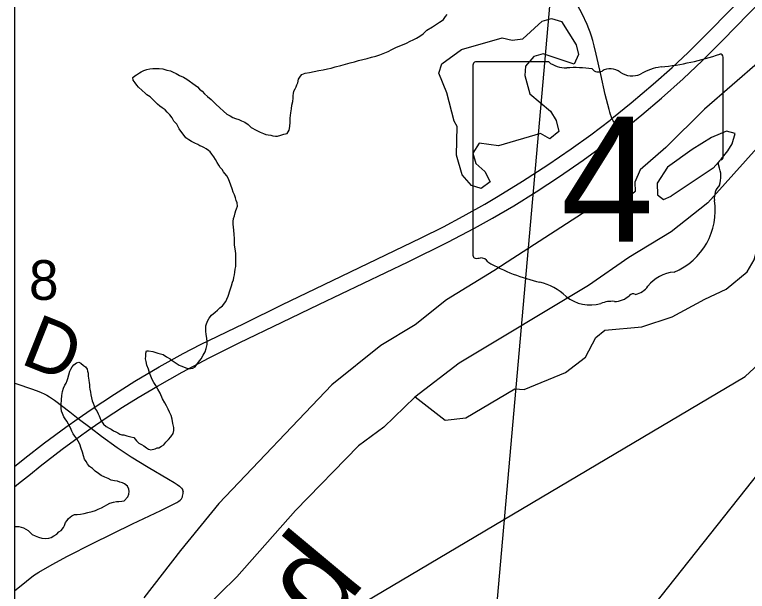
# Model space of a CAD drawing. Extents: x 0 to 34, y 0 to 22.
# Drawn here: x 22.516 to 23.289, y 17.166 to 17.774 of the extents above; entities that cross this region are included whole.
import ezdxf

# ---------------------------------------------------------------- set-up
doc = ezdxf.new("R2010")
doc.units = 0
for name, color, linetype in [('GM_X_County_Road', 7, 'Continuous'), ('GM_X_Major_River', 7, 'Continuous'), ('GM_X_Major_River_Text', 7, 'Continuous'), ('GM_X_Minor_Lake', 7, 'Continuous'), ('GM_X_Minor_River', 7, 'Continuous'), ('GM_X_Rail_Line', 7, 'Continuous'), ('GM_X_Section', 7, 'Continuous'), ('GM_X_Section_Text', 7, 'Continuous'), ('GM_X_State_Location', 7, 'Continuous'), ('GM_X_State_Route', 7, 'Continuous'), ('GM_X_State_Shield', 7, 'Continuous'), ('GM_X_Township_Road', 7, 'Continuous'), ('GM_X_Township_Road_Text', 7, 'Continuous'), ('SH_Border', 7, 'Continuous'), ('SH_Data', 7, 'Continuous')]:
    doc.layers.add(name, color=color, linetype=linetype)

msp = doc.modelspace()

# ---------------------------------------------------------------- linework, layer by layer
at = {"layer": 'GM_X_County_Road'}
msp.add_lwpolyline([(22.51637, 18.01675), (22.51637, 17.0024), (23.00697, 16.95129), (23.09601, 17.95858)], close=True, dxfattribs=at)
at = {"layer": 'GM_X_Major_River'}
for points in [[(23.30177, 17.72504), (23.24359, 17.67462), (23.20273, 17.63398), (23.17558, 17.61042), (23.16994, 17.59767), (23.17045, 17.58779), (23.15958, 17.57822), (23.13867, 17.57575), (23.11487, 17.56462), (23.03543, 17.51325), (23.02154, 17.50413), (22.97146, 17.4736), (22.93855, 17.44716), (22.90234, 17.42536), (22.85084, 17.38386), (22.73158, 17.25878), (22.69125, 17.20938), (22.65243, 17.15956)], [(23.31427, 17.65071), (23.24713, 17.57586), (23.20842, 17.5454), (23.16373, 17.51814), (23.12126, 17.48855), (22.98491, 17.40682), (22.9381, 17.37089), (22.90544, 17.3395), (22.87877, 17.31973), (22.81255, 17.25167), (22.75046, 17.1816), (22.71467, 17.1465), (22.65709, 17.07555), (22.63645, 17.05447), (22.62333, 17.04533), (22.57284, 17.02884), (22.56247, 17.01292)], [(23.25271, 17.61242), (23.26124, 17.62174), (23.26825, 17.63072), (23.27257, 17.63785), (23.27582, 17.6488), (23.26677, 17.65127), (23.25108, 17.64475), (23.23072, 17.63187), (23.20455, 17.61341), (23.19359, 17.59653), (23.1941, 17.58436), (23.20045, 17.57929), (23.20849, 17.58293)], [(23.25271, 17.61242), (23.20849, 17.58293)]]:
    msp.add_lwpolyline(points, dxfattribs=at)
at = {"layer": 'GM_X_Minor_Lake'}
for points in [[(22.97208, 17.6919), (22.96339, 17.71259), (22.96662, 17.72241), (22.98741, 17.73756), (23.03014, 17.7496), (23.04071, 17.7471), (23.05212, 17.74877), (23.0726, 17.76735), (23.08214, 17.77019), (23.0927, 17.76693), (23.10814, 17.7423), (23.11058, 17.73199), (23.10621, 17.72182), (23.07342, 17.73275), (23.0635, 17.72992), (23.05495, 17.71983), (23.054, 17.70997), (23.0593, 17.69087), (23.08132, 17.67255), (23.08718, 17.66256), (23.08999, 17.6511), (23.08035, 17.64332), (23.0706, 17.64883), (23.02633, 17.63606), (23.0059, 17.63876), (22.99925, 17.62826), (23.00244, 17.61717), (23.01213, 17.609), (23.0176, 17.59786), (23.00798, 17.59084), (22.9978, 17.59409), (22.98816, 17.60531), (22.98213, 17.62595), (22.98274, 17.65634), (22.97981, 17.66172)], [(22.97981, 17.66172), (22.97208, 17.6919)]]:
    msp.add_lwpolyline(points, dxfattribs=at)
at = {"layer": 'GM_X_Minor_River'}
for points in [[(22.91822, 17.73947), (22.9293, 17.74423), (22.93313, 17.74607), (22.93657, 17.74753), (22.94001, 17.74938), (22.94347, 17.7516), (22.94692, 17.75382), (22.95078, 17.75794), (22.95691, 17.76126), (22.96113, 17.76424), (22.9642, 17.76608), (22.96611, 17.76719), (22.96842, 17.76906), (22.97037, 17.77207), (22.9723, 17.77432)], [(22.66486, 17.68205), (22.66186, 17.68476), (22.65925, 17.68747), (22.65587, 17.6898), (22.65399, 17.69135), (22.65062, 17.69407), (22.64688, 17.69756), (22.64502, 17.69987), (22.64354, 17.70217), (22.64131, 17.70525), (22.64097, 17.70792), (22.6429, 17.70979), (22.64482, 17.7109), (22.64788, 17.71275), (22.6498, 17.71386), (22.65248, 17.71533), (22.65554, 17.71642), (22.65896, 17.71713), (22.66201, 17.71746), (22.66542, 17.7174), (22.66883, 17.71735), (22.67262, 17.7169), (22.67678, 17.71569), (22.68056, 17.71487), (22.68358, 17.71368), (22.68659, 17.71211), (22.68998, 17.71015), (22.6945, 17.70818), (22.69789, 17.70622), (22.70652, 17.7), (22.70915, 17.69805), (22.71139, 17.69573), (22.71401, 17.69341), (22.71662, 17.6907), (22.71962, 17.688), (22.72336, 17.68489), (22.7286, 17.67986), (22.73271, 17.67599), (22.73645, 17.67251), (22.7402, 17.66941), (22.74358, 17.66745), (22.74622, 17.66589), (22.74923, 17.66469), (22.75263, 17.6635), (22.75565, 17.66231), (22.75904, 17.66073), (22.76242, 17.65839), (22.76579, 17.6553), (22.77106, 17.65255), (22.7752, 17.6502), (22.77859, 17.649), (22.78123, 17.64782), (22.78351, 17.6474), (22.78653, 17.64697), (22.78842, 17.64656), (22.79145, 17.64613), (22.79335, 17.6461), (22.79679, 17.64718), (22.80022, 17.64827), (22.80365, 17.64897), (22.8056, 17.65236), (22.80642, 17.65615), (22.80687, 17.6607), (22.80694, 17.66489), (22.80741, 17.67058), (22.80823, 17.67475), (22.80868, 17.67892), (22.8095, 17.68271), (22.80993, 17.68613), (22.80998, 17.68879), (22.81039, 17.69106), (22.81081, 17.69334), (22.81199, 17.69598), (22.81317, 17.69824), (22.81396, 17.70013), (22.81475, 17.7024), (22.81557, 17.70619), (22.81752, 17.70919), (22.81906, 17.71107), (22.8225, 17.71253), (22.82707, 17.71322), (22.83202, 17.71428), (22.83697, 17.71534), (22.84154, 17.71602), (22.84611, 17.71709), (22.84992, 17.71778), (22.85412, 17.71924), (22.86022, 17.72066), (22.86518, 17.7221), (22.87013, 17.72353), (22.87471, 17.7246), (22.8789, 17.72567), (22.88347, 17.72674), (22.88804, 17.7278), (22.89262, 17.72925), (22.89719, 17.73031), (22.90139, 17.73176), (22.90483, 17.73323), (22.91018, 17.73542), (22.91401, 17.73726), (22.91822, 17.73947)], [(22.69796, 17.40166), (22.69985, 17.40125), (22.70175, 17.40122), (22.70403, 17.40156), (22.70672, 17.40304), (22.70789, 17.40492), (22.71021, 17.40792), (22.71292, 17.4113), (22.71526, 17.41507), (22.71722, 17.41884), (22.71841, 17.42224), (22.71924, 17.42641), (22.71929, 17.42945), (22.71897, 17.43325), (22.71827, 17.43707), (22.71794, 17.4405), (22.71799, 17.44354), (22.71803, 17.4462), (22.71844, 17.44809), (22.71923, 17.44998), (22.72002, 17.45187), (22.72158, 17.45412), (22.72391, 17.45751), (22.72775, 17.46049), (22.73007, 17.46273), (22.73276, 17.46497), (22.73545, 17.46721), (22.73894, 17.47171), (22.74012, 17.47435), (22.74131, 17.47738), (22.7437, 17.48418), (22.7449, 17.48834), (22.7461, 17.49213), (22.7469, 17.49478), (22.74732, 17.49705), (22.74813, 17.50008), (22.74855, 17.50273), (22.74897, 17.50577), (22.7494, 17.5088), (22.74946, 17.51222), (22.74951, 17.51526), (22.74955, 17.51793), (22.74958, 17.52021), (22.74961, 17.52211), (22.74928, 17.52515), (22.74893, 17.52706), (22.74825, 17.53164), (22.74829, 17.53392), (22.74797, 17.5381), (22.74766, 17.54229), (22.74735, 17.54686), (22.74703, 17.55028), (22.7467, 17.55333), (22.74674, 17.55599), (22.74717, 17.55941), (22.74797, 17.56206), (22.74878, 17.56509), (22.74958, 17.56774), (22.75037, 17.56962), (22.75118, 17.57227), (22.75085, 17.5757), (22.74975, 17.57838), (22.74904, 17.58105), (22.74795, 17.58411), (22.74686, 17.58717), (22.74577, 17.59061), (22.74432, 17.59444), (22.74286, 17.59826), (22.7414, 17.60171), (22.73992, 17.60439), (22.73806, 17.60671), (22.73657, 17.60863), (22.73509, 17.61094), (22.73284, 17.61288), (22.73175, 17.61555), (22.72989, 17.61825), (22.72804, 17.62132), (22.72619, 17.62439), (22.72434, 17.62708), (22.72248, 17.6294), (22.7206, 17.63095), (22.71836, 17.63288), (22.71572, 17.63407), (22.71384, 17.63524), (22.71157, 17.63604), (22.70931, 17.63721), (22.7063, 17.63879), (22.70291, 17.64036), (22.69991, 17.64231), (22.6969, 17.64426), (22.68984, 17.65389), (22.68726, 17.65887), (22.68428, 17.66196), (22.68243, 17.66541), (22.67983, 17.6685), (22.67721, 17.6712), (22.67497, 17.6739), (22.67197, 17.67585), (22.66934, 17.6778), (22.6671, 17.67973), (22.66486, 17.68205)], [(22.93871, 17.37135), (22.97006, 17.34689), (22.99211, 17.3491), (23.04355, 17.37959), (23.0534, 17.379), (23.09702, 17.39711), (23.1182, 17.41302), (23.12886, 17.4337), (23.1385, 17.44148), (23.17765, 17.44524), (23.20934, 17.45561), (23.24386, 17.47428), (23.26645, 17.48484), (23.28844, 17.50301), (23.29591, 17.51578), (23.31067, 17.57057), (23.3356, 17.60312), (23.35611, 17.6236), (23.36651, 17.63136), (23.39736, 17.65619), (23.41867, 17.65955), (23.43828, 17.65383)], [(22.56779, 17.3806), (22.56936, 17.38361), (22.57054, 17.38588), (22.57172, 17.38852), (22.57251, 17.39078), (22.57453, 17.39836), (22.57571, 17.40062), (22.57688, 17.40288), (22.57882, 17.40513), (22.5815, 17.40699), (22.58417, 17.40771), (22.58606, 17.40691), (22.58905, 17.40421), (22.59093, 17.40303), (22.59279, 17.40034), (22.59314, 17.39843), (22.59386, 17.39614), (22.59381, 17.3931), (22.5945, 17.38891), (22.59484, 17.38624), (22.59519, 17.38433), (22.59515, 17.38167), (22.59549, 17.37938), (22.5962, 17.37633), (22.59653, 17.37328), (22.59724, 17.37023), (22.59795, 17.36717), (22.59904, 17.3645), (22.60014, 17.36181), (22.60123, 17.35875), (22.60309, 17.35644), (22.60456, 17.35338), (22.60529, 17.35146), (22.60602, 17.34955), (22.60711, 17.34687), (22.6086, 17.34457), (22.61009, 17.34264), (22.6127, 17.33993), (22.61609, 17.33836), (22.61797, 17.33719), (22.6206, 17.33562), (22.62286, 17.33445), (22.62512, 17.33327), (22.62738, 17.33209), (22.62926, 17.3313), (22.63154, 17.33126), (22.63456, 17.33007), (22.63872, 17.32924), (22.64213, 17.32843), (22.64473, 17.32496), (22.64735, 17.32264), (22.64998, 17.32107), (22.65261, 17.31951), (22.65524, 17.31757), (22.65749, 17.31601), (22.65976, 17.31559), (22.66433, 17.31666), (22.66662, 17.31738), (22.66853, 17.31773), (22.67121, 17.31921), (22.67351, 17.32069), (22.67584, 17.32369), (22.67854, 17.32631), (22.68086, 17.32931), (22.68357, 17.33269), (22.684, 17.33573), (22.68406, 17.33915), (22.68298, 17.34335), (22.6823, 17.34792), (22.68122, 17.35174), (22.67976, 17.35519), (22.67829, 17.35825), (22.67644, 17.36171), (22.6746, 17.36516), (22.67239, 17.36938), (22.66983, 17.37512), (22.66724, 17.37935), (22.66502, 17.38319), (22.66317, 17.38626), (22.66133, 17.38971), (22.65986, 17.39316), (22.6584, 17.3966), (22.65732, 17.40042), (22.65587, 17.40463), (22.65517, 17.40844), (22.65446, 17.4115), (22.65451, 17.41416), (22.65455, 17.4172), (22.65536, 17.41985), (22.65763, 17.41981), (22.66217, 17.41898), (22.66746, 17.41737), (22.67275, 17.41576), (22.67651, 17.41342), (22.68028, 17.41146), (22.68252, 17.40952), (22.6844, 17.40835), (22.68778, 17.40601), (22.68966, 17.40484), (22.69155, 17.40405), (22.69796, 17.40166)], [(22.51637, 17.23463), (22.51649, 17.23465), (22.52066, 17.23459), (22.52558, 17.23337), (22.52821, 17.2318), (22.53047, 17.23025), (22.53271, 17.22831), (22.53496, 17.22637), (22.53797, 17.2248), (22.54136, 17.22322), (22.54515, 17.2224), (22.54856, 17.22196), (22.55236, 17.22228), (22.55503, 17.223), (22.55771, 17.22486), (22.56078, 17.22671), (22.56309, 17.22895), (22.5654, 17.23043), (22.56772, 17.23344), (22.5689, 17.2357), (22.57008, 17.23872), (22.57164, 17.24098), (22.57319, 17.24324), (22.57665, 17.24584), (22.57933, 17.24732), (22.58237, 17.24727), (22.58579, 17.24759), (22.5896, 17.24829), (22.59341, 17.24937), (22.59798, 17.25044), (22.60142, 17.25152), (22.60448, 17.25299), (22.60792, 17.25446), (22.61098, 17.25593), (22.61366, 17.25741), (22.61672, 17.25926), (22.62054, 17.26033), (22.62359, 17.26105), (22.62624, 17.261), (22.62929, 17.26133), (22.63195, 17.26167), (22.63581, 17.26579), (22.63662, 17.26882), (22.63704, 17.27147), (22.6367, 17.27414), (22.63523, 17.27721), (22.63223, 17.27954), (22.62997, 17.28071), (22.62733, 17.28152), (22.62469, 17.28232), (22.62166, 17.28275), (22.61825, 17.28357), (22.61486, 17.28514), (22.61147, 17.28672), (22.6077, 17.2883), (22.6047, 17.29063), (22.60132, 17.29297), (22.59833, 17.29568), (22.59533, 17.29801), (22.59309, 17.30071), (22.59161, 17.30302), (22.59014, 17.3057), (22.58905, 17.30914), (22.58797, 17.31296), (22.58651, 17.31679), (22.58507, 17.32137), (22.58322, 17.32445), (22.58175, 17.32713), (22.57989, 17.32982), (22.57803, 17.33214), (22.57656, 17.3352), (22.5751, 17.33865), (22.57326, 17.34248), (22.57141, 17.34555), (22.56956, 17.34825), (22.56807, 17.35017), (22.56698, 17.35361), (22.56589, 17.35629), (22.56556, 17.35934), (22.56524, 17.36315), (22.5657, 17.36808), (22.56615, 17.37264), (22.56697, 17.37681), (22.56779, 17.3806)]]:
    msp.add_lwpolyline(points, dxfattribs=at)
at = {"layer": 'GM_X_Rail_Line'}
for points in [[(22.51637, 16.93545), (22.62022, 16.9977), (23.2863, 17.39264), (23.9265, 17.98458), (25.28936, 19.3687), (25.68844, 19.73766)], [(22.51637, 16.40146), (22.60404, 16.47321), (22.68043, 16.53593), (22.99636, 16.90708), (23.39125, 17.4049), (25.21918, 19.26631), (25.71658, 19.73499)]]:
    msp.add_lwpolyline(points, dxfattribs=at)
at = {"layer": 'GM_X_Section'}
msp.add_lwpolyline([(24.0891, 17.85881), (23.98418, 16.85292), (23.00697, 16.95129), (23.09601, 17.95858)], close=True, dxfattribs=at)
at = {"layer": 'GM_X_State_Route'}
msp.add_line((22.58703, 17.33109), (22.58868, 17.3323), dxfattribs=at)
for points in [[(22.63011, 17.36055), (22.64647, 17.37072), (22.66685, 17.38266), (22.6929, 17.3972), (22.72147, 17.41231), (22.75312, 17.42819), (22.79844, 17.45009), (22.83705, 17.46871), (22.93121, 17.51373), (22.97292, 17.53448), (23.00102, 17.54908), (23.02005, 17.55955), (23.04256, 17.57269), (23.06628, 17.58744), (23.09067, 17.60345), (23.11568, 17.62077), (23.13772, 17.63691), (23.15588, 17.65097), (23.15833, 17.65287), (23.1776, 17.66852), (23.19836, 17.68627), (23.22097, 17.70662), (23.24129, 17.7258), (23.26242, 17.74681), (23.33158, 17.81819)], [(22.51637, 17.2979), (22.5271, 17.30672), (22.5477, 17.3227), (22.57021, 17.33925), (22.58342, 17.3485), (22.59715, 17.35813), (22.6215, 17.37419), (22.64308, 17.38767), (22.66872, 17.40283), (22.69417, 17.41707), (22.71233, 17.42651), (22.75819, 17.44861), (22.79887, 17.46865), (22.83305, 17.48501), (22.94505, 17.53884), (22.96845, 17.55044), (22.98928, 17.5616), (23.01198, 17.57453), (23.02589, 17.58275), (23.05183, 17.59873), (23.07847, 17.61592), (23.10316, 17.63269), (23.12388, 17.64756), (23.14414, 17.66305), (23.14604, 17.66455), (23.16638, 17.68104), (23.18961, 17.70075), (23.2096, 17.71852), (23.22633, 17.73431), (23.24886, 17.75663), (23.3079, 17.8171)], [(22.58868, 17.3323), (22.5895, 17.33291), (22.59697, 17.33813), (22.61193, 17.34858), (22.63011, 17.36055)], [(22.53309, 17.28994), (22.54329, 17.29816), (22.56645, 17.31599), (22.58703, 17.33109)], [(22.51637, 17.27631), (22.52053, 17.27983), (22.53309, 17.28994)]]:
    msp.add_lwpolyline(points, dxfattribs=at)
at = {"layer": 'GM_X_State_Shield'}
for p, q in [((23.26316, 17.62461), (23.26316, 17.7293)), ((22.9995, 17.7209), (22.9995, 17.52078)), ((23.07931, 17.72434), (23.00209, 17.72434)), ((23.26314, 17.62464), (23.26316, 17.62461))]:
    msp.add_line(p, q, dxfattribs=at)
for centre, radius, start, end in [((23.16924, 17.99717), 0.27962, 275.84447, 288.90645), ((23.26024, 17.72973), 0.00294, 351.86209, 97.738), ((23.00252, 17.72132), 0.00305, 98.1301, 188.1301), ((23.0977, 17.74757), 0.02963, 231.61951, 271.11188), ((23.10752, 17.61199), 0.10636, 80.48669, 94.98827), ((23.20491, 17.66322), 0.05625, 97.34618, 120.76885), ((23.13167, 17.72236), 0.00855, 219.79206, 297.10237), ((23.14422, 17.69923), 0.01777, 54.46668, 119.14113), ((23.16715, 17.73096), 0.02138, 233.85621, 294.82819), ((23.26249, 17.61693), 0.00454, 107.94398, 210.33697), ((23.26003, 17.62421), 0.00314, 289.60381, 7.73413), ((23.23359, 17.6037), 0.02727, 340.03296, 23.64957), ((23.27368, 17.5808), 0.01984, 136.8065, 186.92959), ((23.18491, 17.56749), 0.06994, 292.30889, 8.98584), ((23.00255, 17.52034), 0.00308, 171.95839, 258.30661), ((23.00301, 17.54081), 0.02352, 267.33899, 280.60386), ((23.00782, 17.50923), 0.00848, 29.74838, 93.27175), ((23.11488, 17.68903), 0.20192, 240.41292, 257.1985), ((23.21439, 17.46459), 0.0383, 94.40312, 142.57675), ((23.05468, 17.43087), 0.06318, 47.18416, 75.83597), ((23.16586, 17.50138), 0.0226, 282.87319, 323.27711), ((23.14911, 17.49325), 0.02136, 268.77702, 315.54927), ((23.16843, 17.47387), 0.00601, 65.75173, 132.64842), ((23.12301, 17.50824), 0.04009, 230.70037, 286.29184), ((23.14618, 17.43905), 0.03294, 85.69512, 111.20995)]:
    msp.add_arc(centre, radius, start, end, dxfattribs=at)
at = {"layer": 'GM_X_Township_Road'}
for points in [[(23.14604, 17.66455), (23.14541, 17.66593), (23.14437, 17.66893), (23.14367, 17.67141), (23.14292, 17.67434), (23.13891, 17.69002), (23.13415, 17.71125), (23.12947, 17.73247), (23.12731, 17.74114), (23.1258, 17.74688), (23.12442, 17.75142), (23.12297, 17.75568), (23.12163, 17.75935), (23.11978, 17.76371), (23.11449, 17.77489), (23.10163, 17.79967), (23.09034, 17.81965), (23.08774, 17.82397), (23.08532, 17.82774)], [(23.15588, 17.65097), (23.154, 17.65347), (23.14904, 17.66005), (23.14737, 17.66241), (23.14604, 17.66455)], [(22.51637, 17.38557), (22.51757, 17.38523), (22.53532, 17.3795), (22.54187, 17.37697), (22.54424, 17.37591), (22.54751, 17.37435), (22.55013, 17.37304), (22.55304, 17.37133), (22.55821, 17.36783), (22.57444, 17.35537), (22.58342, 17.3485), (22.59697, 17.33813), (22.60781, 17.32984), (22.62434, 17.3179), (22.63923, 17.30824), (22.65707, 17.29719), (22.67855, 17.28466), (22.68454, 17.28109), (22.68775, 17.27887), (22.69025, 17.277), (22.69227, 17.275), (22.69314, 17.27377), (22.69347, 17.27313), (22.69378, 17.27239), (22.69397, 17.27125)], [(22.51637, 17.16668), (22.51803, 17.16808), (22.52869, 17.17694), (22.53614, 17.18283), (22.54178, 17.18667), (22.55606, 17.19475), (22.57213, 17.20321), (22.59847, 17.21654), (22.64074, 17.23732), (22.67037, 17.25135), (22.68449, 17.25841), (22.68746, 17.26006), (22.68935, 17.26123), (22.69086, 17.26256), (22.69209, 17.26392), (22.69291, 17.26521), (22.69319, 17.2658), (22.69347, 17.26663), (22.69374, 17.26796), (22.69392, 17.26951), (22.69397, 17.27125)]]:
    msp.add_lwpolyline(points, dxfattribs=at)
at = {"layer": 'SH_Border'}
msp.add_lwpolyline([(22.51637, 19.03183), (22.51637, 14.97433)], dxfattribs=at)
at = {"layer": 'SH_Data'}
msp.add_line((22.51637, 20.26181), (22.51637, 13.46181), dxfattribs=at)
msp.add_lwpolyline([(22.51637, 19.03183), (22.51637, 13.46181)], dxfattribs=at)

# ---------------------------------------------------------------- texts
at = {"layer": 'GM_X_Major_River_Text'}
msp.add_text('Mad', height=0.094751, rotation=50.19861, dxfattribs=at).set_placement((22.72946, 16.98675))
at = {"layer": 'GM_X_Section_Text'}
msp.add_text('8', height=0.04186, rotation=0.00001, dxfattribs=at).set_placement((22.5315, 17.47353))
at = {"layer": 'GM_X_State_Location'}
for s, p in [('s', (23.12836, 17.60753)), ('r', (23.12835, 17.60753))]:
    msp.add_text(s, height=0.000189, dxfattribs=at).set_placement(p)
msp.add_text('4', height=0.000189, rotation=0.00001, dxfattribs=at).set_placement((23.09983, 17.59375))
at = {"layer": 'GM_X_State_Shield'}
msp.add_text('4', height=0.13184, dxfattribs=at).set_placement((23.09217, 17.53489))
at = {"layer": 'GM_X_Township_Road_Text'}
msp.add_text('D', height=0.05682, rotation=338.34132, dxfattribs=at).set_placement((22.52103, 17.40677))

doc.saveas('drawing.dxf')
